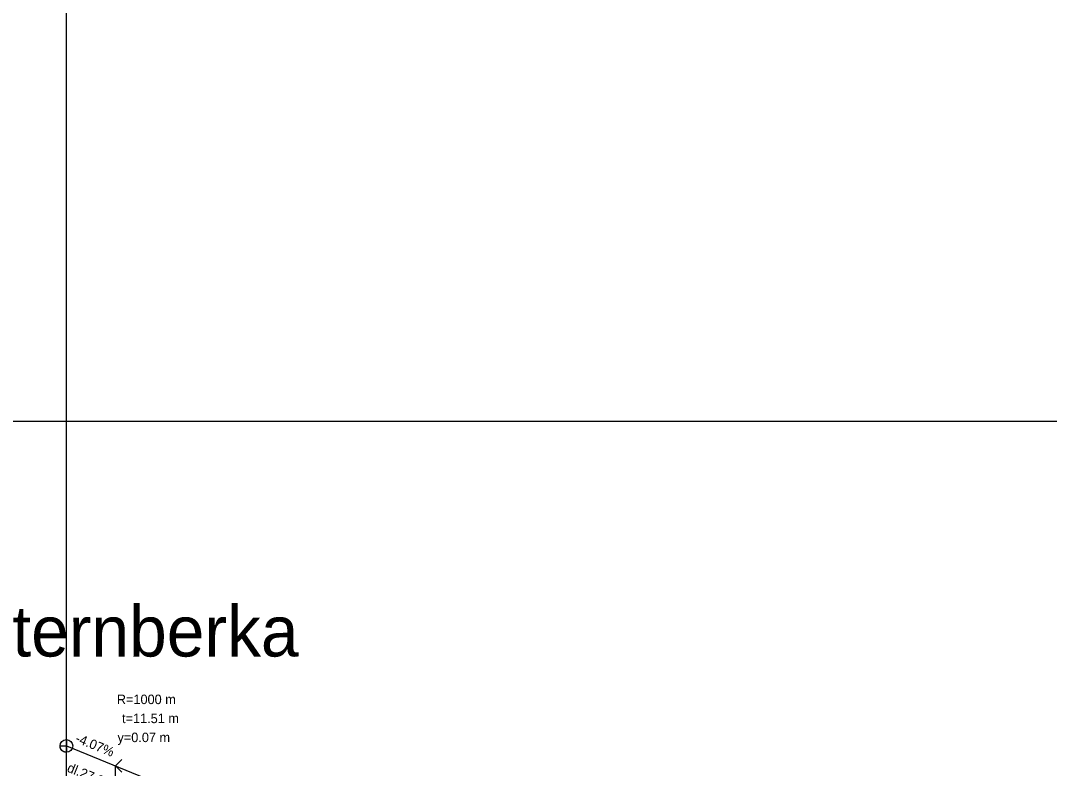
# Model space of a CAD drawing. Extents: x -550605 to -538780, y -1102367 to -1093705.
# Drawn here: x -541409.3 to -541084.3, y -1097216.8 to -1096980.7 of the extents above; entities that cross this region are included whole.
import ezdxf

# ---------------------------------------------------------------- set-up
doc = ezdxf.new("R2010")
doc.units = 0
for name, color, linetype in [('PP - názvy', 7, 'Continuous'), ('PP - popis', 7, 'Continuous'), ('Vrstva 57 - Ohrada pro tisk', 7, 'Continuous')]:
    doc.layers.add(name, color=color, linetype=linetype)

msp = doc.modelspace()

# ---------------------------------------------------------------- linework, layer by layer
at = {"layer": 'PP - popis'}
for p, q in [((-541394.8, -1097570.66), (-541394.8, -1093720.66)), ((-541394.8, -1097209.66), (-541394.8, -1097209.66)), ((-541394.8, -1097209.66), (-541367.8, -1097220.66)), ((-541394.8, -1097309.66), (-541394.8, -1097209.66)), ((-541379.31, -1097315.97), (-541379.31, -1097215.97))]:
    msp.add_line(p, q, dxfattribs=at)
msp.add_lwpolyline([(-541394.8, -1097209.66), (-541394.8, -1097207.66), (-541394.8, -1097209.66), (-541394.8, -1097211.66), (-541394.93, -1097211.65), (-541395.05, -1097211.64), (-541395.18, -1097211.62), (-541395.31, -1097211.59), (-541395.43, -1097211.56), (-541395.55, -1097211.51), (-541395.67, -1097211.46), (-541395.78, -1097211.4), (-541395.89, -1097211.33), (-541395.99, -1097211.26), (-541396.09, -1097211.18), (-541396.19, -1097211.1), (-541396.28, -1097211), (-541396.36, -1097210.91), (-541396.44, -1097210.8), (-541396.51, -1097210.7), (-541396.57, -1097210.58), (-541396.63, -1097210.47), (-541396.67, -1097210.35), (-541396.72, -1097210.23), (-541396.75, -1097210.1), (-541396.77, -1097209.98), (-541396.79, -1097209.85), (-541396.8, -1097209.72), (-541396.8, -1097209.66)], close=True, dxfattribs=at)
msp.add_lwpolyline([(-541377.31, -1097213.97), (-541379.31, -1097215.97), (-541377.31, -1097217.97)], dxfattribs=at)
msp.add_circle((-541394.8, -1097209.66), 2, dxfattribs=at)
at = {"layer": 'Vrstva 57 - Ohrada pro tisk'}
msp.add_lwpolyline([(-541634.97, -1097677.25), (-538779.82, -1097677.25), (-538779.81, -1097107.25), (-541634.97, -1097107.25)], close=True, dxfattribs=at)

# ---------------------------------------------------------------- texts
at = {"layer": 'PP - názvy'}
msp.add_text('KPÚ v k.ú. Paseka u Šternberka', height=16, dxfattribs=at).set_placement((-541628.29, -1097181.44))
at = {"layer": 'PP - popis'}
for s, p in [('R=1000 m', (-541378.86, -1097196.47)), ('t=11.51 m', (-541377.21, -1097202.47)), ('y=0.07 m', (-541378.66, -1097208.47))]:
    msp.add_text(s, height=3, dxfattribs=at).set_placement(p)
for s, p in [('-4.07%', (-541392.23, -1097208.37)), ('dl.27.00 m', (-541394.82, -1097217.68))]:
    msp.add_text(s, height=3, rotation=337.8337, dxfattribs=at).set_placement(p)

doc.saveas('drawing.dxf')
